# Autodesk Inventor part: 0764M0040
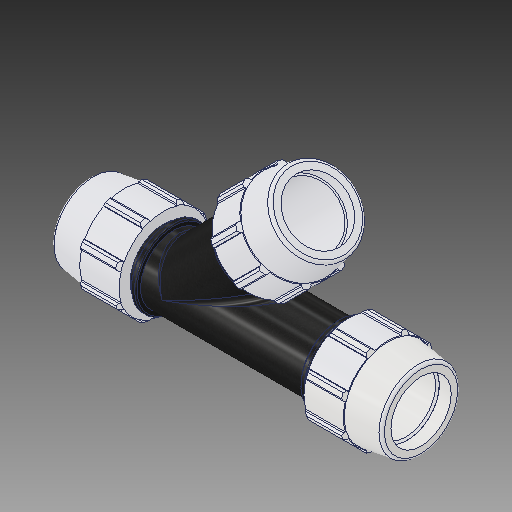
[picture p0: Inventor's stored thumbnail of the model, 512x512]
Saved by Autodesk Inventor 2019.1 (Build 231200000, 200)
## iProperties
Created: 2017-02
Part Number: 0764M0040
Material: PVC-Piping
Description: PLASSON 45° TEE 4'' - 4'' - 4''
Document SubType Name: Modeling
Designer: KIM
Mass: 92.6774 g
Surface Area: 199.44 cm^2
Volume: 66.1981 cm^3
Density: 1.4 g/cm^3
Appearance: PTFE
Author: Кирилл
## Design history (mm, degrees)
derived "0764M0.ipt"
feature "Solid1::0764M0.ipt"
feature "Solid3::0764M0.ipt"
tag "TaggingFeature1"
body "Solid1"
other parameters: "d2" = 114.1, "d4" = 26.04558, "d5" = 62.5094, "d7" = 181.102, "d11" = 10.41823, "d13" = 120 deg, "d14" = 148.33, "d15" = 8 deg, "d16" = 144.8816, "d18" = 5.705, "d19" = 35 deg, "d20" = 17.5 deg, "d21" = 168.42486, "d23" = 0, "d25" = 360 deg, "d27" = 3.62204, "d33" = 2.282, "d42" = 75.01128, "d43" = 5.43306, "d46" = 3.423, "d68" = 9.37641, "d91" = 126.7714, "d93" = 194.056, "d95" = 102.69, "d134" = 312.547, "d138" = 45 deg, "d141" = 283.972, "d144" = 0, "d146" = 0, "d150" = 5.705, "d158" = 11.41, "d165" = 426.9232, "d166" = 168.42486, "d167" = 35 deg, "d168" = 17.5 deg, "d170" = 0, "d172" = 360 deg, "d174" = 5.43306, "d177" = 3.62204, "d_" = 114.1, "E_" = 181.102, "A_" = 283.972, "l_" = 194.056, "H_" = 625.094
